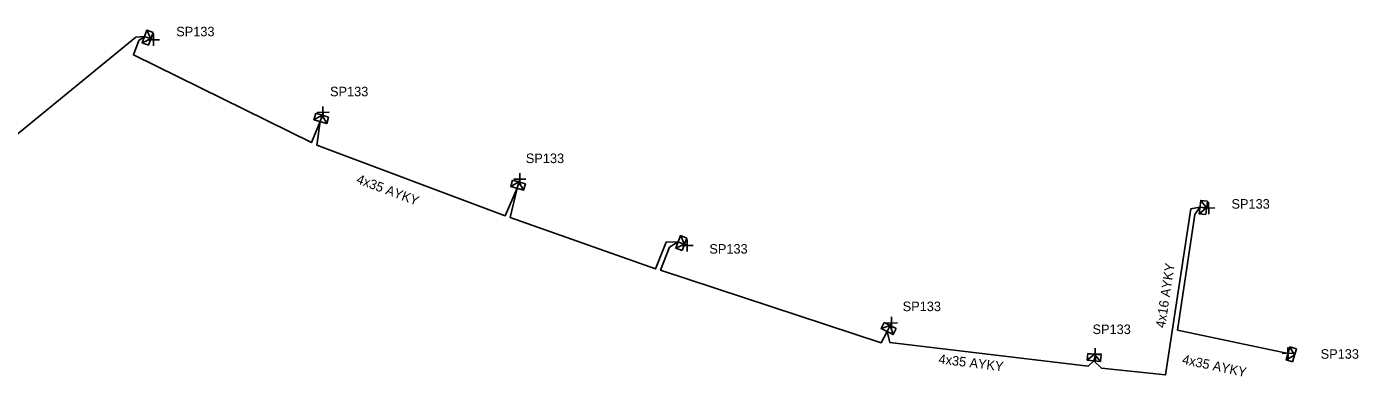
# Model space of a CAD drawing. Extents: x -762503 to -762212, y -1153994 to -1153331.
# Drawn here: x -762363.4 to -762224.5, y -1153639.5 to -1153603 of the extents above; entities that cross this region are included whole.
import ezdxf

# ---------------------------------------------------------------- set-up
doc = ezdxf.new("R2010")
doc.units = 0
for name, color, linetype in [('Vrstva 31', 7, 'Continuous'), ('Vrstva 33', 7, 'Continuous'), ('Vrstva 34', 7, 'Continuous'), ('Vrstva 5', 7, 'Continuous'), ('Vrstva 52', 7, 'Continuous'), ('Vrstva 54', 7, 'Continuous'), ('Vrstva 59', 7, 'Continuous'), ('Vrstva 6', 7, 'Continuous')]:
    doc.layers.add(name, color=color, linetype=linetype)

msp = doc.modelspace()

# ---------------------------------------------------------------- linework, layer by layer
at = {"layer": 'Vrstva 31'}
for points in [[(-762350.702, -1153604.95), (-762351.36, -1153604.711), (-762350.881, -1153603.395), (-762350.223, -1153603.635)], [(-762350.462, -1153604.293), (-762350.881, -1153603.395)], [(-762350.702, -1153604.95), (-762350.223, -1153603.635)], [(-762350.462, -1153604.293), (-762351.36, -1153604.711)], [(-762331.913, -1153612.466), (-762332.118, -1153613.135), (-762333.456, -1153612.726), (-762333.252, -1153612.057)], [(-762331.913, -1153612.466), (-762333.252, -1153612.057)], [(-762332.582, -1153612.261), (-762333.456, -1153612.726)], [(-762332.582, -1153612.261), (-762332.118, -1153613.135)], [(-762311.392, -1153619.4), (-762311.585, -1153620.073), (-762312.93, -1153619.687), (-762312.737, -1153619.014)], [(-762311.392, -1153619.4), (-762312.737, -1153619.014)], [(-762312.065, -1153619.207), (-762312.93, -1153619.687)], [(-762312.065, -1153619.207), (-762311.585, -1153620.073)], [(-762240.441, -1153622.613), (-762241.135, -1153622.528), (-762240.965, -1153621.138), (-762240.27, -1153621.223)], [(-762240.355, -1153621.918), (-762240.965, -1153621.138)], [(-762240.441, -1153622.613), (-762240.27, -1153621.223)], [(-762240.355, -1153621.918), (-762241.135, -1153622.528)], [(-762295.058, -1153626.367), (-762295.711, -1153626.117), (-762295.21, -1153624.81), (-762294.556, -1153625.06)], [(-762294.807, -1153625.714), (-762295.711, -1153626.117)], [(-762294.807, -1153625.714), (-762295.21, -1153624.81)], [(-762295.058, -1153626.367), (-762294.556, -1153625.06)], [(-762272.731, -1153634.489), (-762273.038, -1153635.118), (-762274.296, -1153634.504), (-762273.989, -1153633.875)], [(-762273.36, -1153634.182), (-762274.296, -1153634.504)], [(-762272.731, -1153634.489), (-762273.989, -1153633.875)], [(-762273.36, -1153634.182), (-762273.038, -1153635.118)], [(-762251.338, -1153637.227), (-762251.411, -1153637.923), (-762252.804, -1153637.777), (-762252.731, -1153637.081)], [(-762251.338, -1153637.227), (-762252.731, -1153637.081)], [(-762231.38, -1153637.948), (-762232.053, -1153637.755), (-762231.667, -1153636.41), (-762230.994, -1153636.603)], [(-762231.187, -1153637.275), (-762231.667, -1153636.41)], [(-762231.38, -1153637.948), (-762230.994, -1153636.603)], [(-762252.034, -1153637.154), (-762252.804, -1153637.777)], [(-762252.034, -1153637.154), (-762251.411, -1153637.923)], [(-762231.187, -1153637.275), (-762232.053, -1153637.755)]]:
    msp.add_lwpolyline(points, dxfattribs=at)
at = {"layer": 'Vrstva 34'}
for points in [[(-762350.805, -1153604.411), (-762349.555, -1153604.389)], [(-762350.169, -1153605.025), (-762350.191, -1153603.775)], [(-762333.125, -1153611.981), (-762331.875, -1153611.959)], [(-762332.489, -1153612.595), (-762332.511, -1153611.345)], [(-762312.605, -1153618.931), (-762311.355, -1153618.909)], [(-762311.969, -1153619.545), (-762311.991, -1153618.295)], [(-762240.119, -1153622.565), (-762240.141, -1153621.315)], [(-762240.755, -1153621.951), (-762239.505, -1153621.929)], [(-762295.155, -1153625.851), (-762293.905, -1153625.829)], [(-762294.519, -1153626.465), (-762294.541, -1153625.215)], [(-762273.845, -1153633.921), (-762272.595, -1153633.899)], [(-762273.209, -1153634.535), (-762273.231, -1153633.285)], [(-762251.939, -1153637.775), (-762251.961, -1153636.525)], [(-762232.485, -1153637.091), (-762231.235, -1153637.069)], [(-762231.849, -1153637.705), (-762231.871, -1153636.455)], [(-762252.575, -1153637.161), (-762251.325, -1153637.139)]]:
    msp.add_lwpolyline(points, dxfattribs=at)
at = {"layer": 'Vrstva 5'}
for points in [[(-762369.69, -1153618.53), (-762352.02, -1153604.12), (-762351.12, -1153604.05), (-762351.71, -1153604.48), (-762352.28, -1153605.98), (-762333.72, -1153615.11), (-762332.79, -1153612.93), (-762333.14, -1153615.38), (-762313.52, -1153622.74), (-762312.26, -1153619.87), (-762312.99, -1153622.92), (-762297.83, -1153628.28), (-762296.73, -1153625.49), (-762295.46, -1153625.46), (-762296.37, -1153626.02), (-762297.3, -1153628.41), (-762274.31, -1153635.99), (-762273.67, -1153634.81), (-762273.38, -1153635.95), (-762252.69, -1153638.43), (-762252.11, -1153637.85)], [(-762252.11, -1153637.85), (-762251.32, -1153638.61), (-762244.63, -1153639.32), (-762242.01, -1153622.03), (-762241.05, -1153621.83)]]:
    msp.add_lwpolyline(points, dxfattribs=at)
at = {"layer": 'Vrstva 52'}
msp.add_lwpolyline([(-762241.05, -1153621.83), (-762241.57, -1153622.61), (-762243.39, -1153634.66), (-762231.86, -1153637.08)], dxfattribs=at)
at = {"layer": 'Vrstva 59'}
for points in [[(-762351.11, -1153604.05), (-762350.18, -1153604.4)], [(-762332.79, -1153612.93), (-762332.5, -1153611.97)], [(-762312.26, -1153619.88), (-762311.98, -1153618.92)], [(-762241.05, -1153621.83), (-762240.13, -1153621.94)], [(-762295.46, -1153625.46), (-762294.53, -1153625.84)], [(-762273.67, -1153634.81), (-762273.22, -1153633.91)], [(-762252.11, -1153637.85), (-762251.95, -1153637.15)]]:
    msp.add_lwpolyline(points, dxfattribs=at)

# ---------------------------------------------------------------- texts
at = {"layer": 'Vrstva 33'}
for p in [(-762347.81, -1153604.04), (-762331.77, -1153610.29), (-762311.35, -1153617.25), (-762237.76, -1153622), (-762292.21, -1153626.69), (-762272.05, -1153632.68), (-762252.25, -1153635.07), (-762228.46, -1153637.64)]:
    msp.add_text('SP133', height=0.9943, dxfattribs=at).set_placement(p)
at = {"layer": 'Vrstva 54'}
msp.add_text('4x35 AYKY', height=0.9943, rotation=348.16844, dxfattribs=at).set_placement((-762242.96, -1153638.16))
at = {"layer": 'Vrstva 6'}
for s, rotation, p in [('4x35 AYKY', 339.44588, (-762329.1, -1153619.31)), ('4x16 AYKY', 81.40183, (-762244.69, -1153634.48)), ('4x35 AYKY', 353.15908, (-762268.35, -1153638.14))]:
    msp.add_text(s, height=0.9943, rotation=rotation, dxfattribs=at).set_placement(p)

doc.saveas('drawing.dxf')
